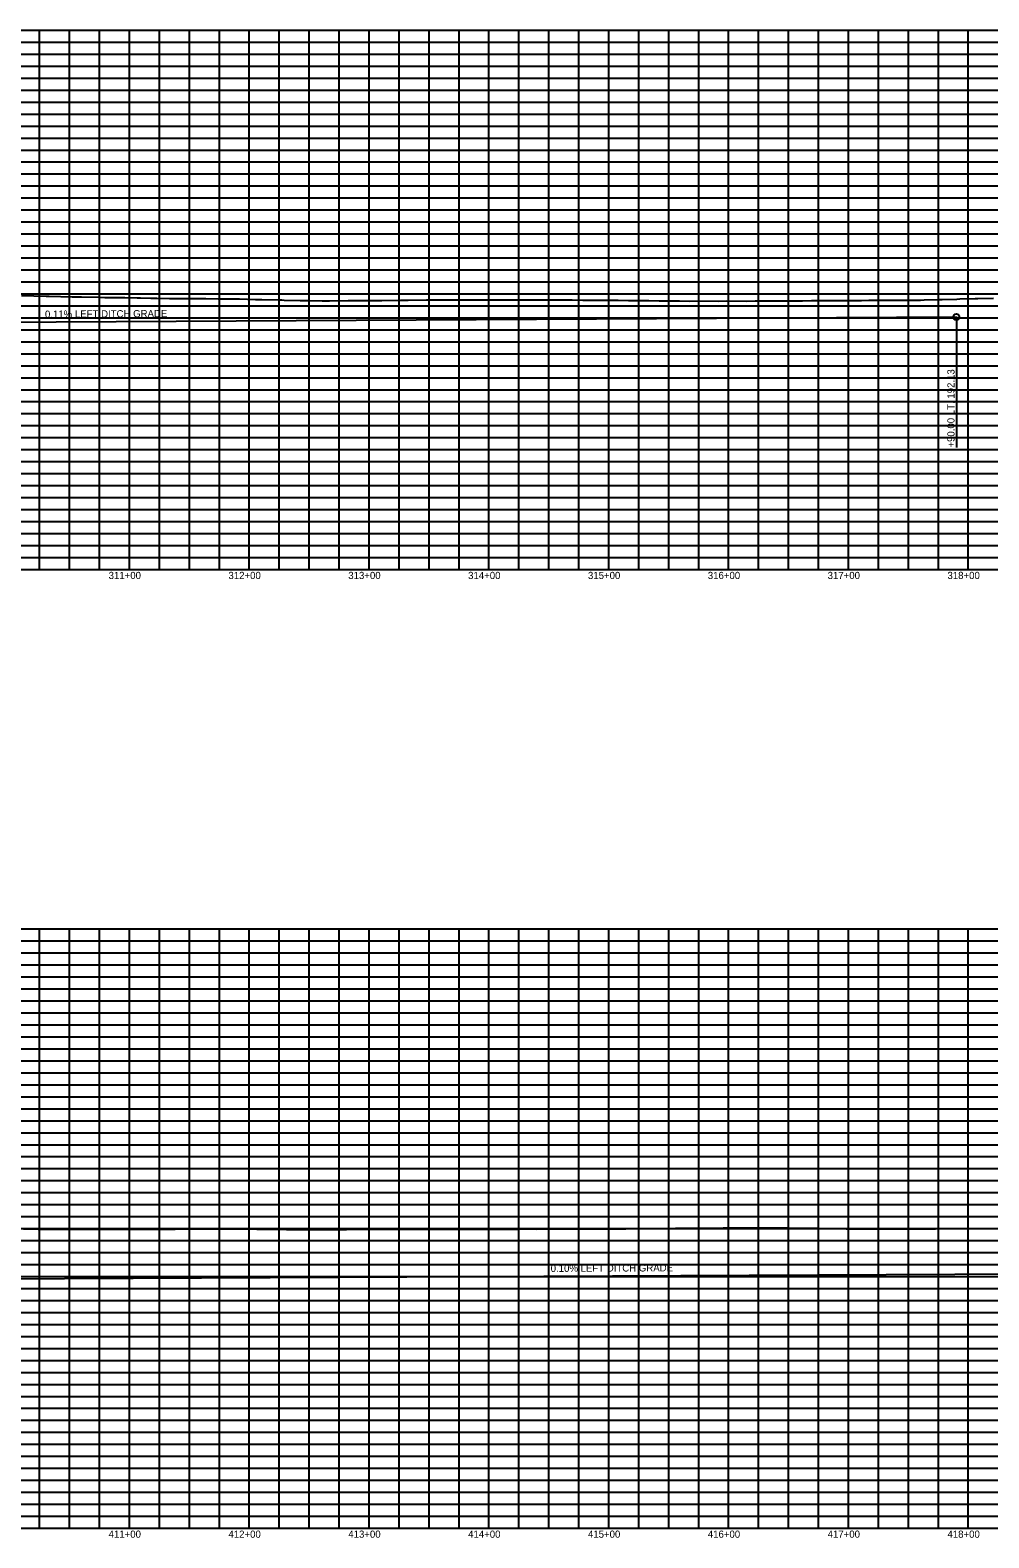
# Model space of a CAD drawing. Extents: x 1399671 to 1408349, y 1930471 to 1933387.
# Drawn here: x 1401341 to 1402141, y 1930471 to 1931729 of the extents above; entities that cross this region are included whole.
import ezdxf

# ---------------------------------------------------------------- set-up
doc = ezdxf.new("R2010")
doc.units = 0
for name, color, linetype in [('R_Exist Surface', 7, 'Continuous'), ('R_Grid', 7, 'Continuous'), ('R_Grid Annot', 7, 'Continuous'), ('R_Vert Alg', 7, 'Continuous'), ('R_Vert Alg Annot', 7, 'Continuous')]:
    doc.layers.add(name, color=color, linetype=linetype)

msp = doc.modelspace()

# ---------------------------------------------------------------- linework, layer by layer
at = {"layer": 'R_Exist Surface'}
for points in [[(1401334, 1931507.1), (1401354.6, 1931506.6), (1401354.6, 1931506.6), (1401357.3, 1931506.5), (1401376.5, 1931506.1), (1401377.1, 1931506.1), (1401380.5, 1931506), (1401384.2, 1931506), (1401398.3, 1931505.7), (1401403.7, 1931505.6), (1401406.3, 1931505.6), (1401417.2, 1931505.4), (1401419.9, 1931505.4), (1401420.2, 1931505.4), (1401430.7, 1931505.2), (1401433.5, 1931505.2), (1401442, 1931505), (1401444.2, 1931505), (1401447.1, 1931505), (1401457.7, 1931504.8), (1401460.7, 1931504.8), (1401463.9, 1931504.8), (1401471.2, 1931504.7), (1401474.2, 1931504.7), (1401484.7, 1931504.6), (1401485.7, 1931504.6), (1401487.8, 1931504.6), (1401498.1, 1931504.5), (1401501.3, 1931504.5), (1401507.6, 1931504.4), (1401511.6, 1931504.4), (1401516.1, 1931504.3), (1401529.4, 1931503.9), (1401530, 1931503.9), (1401534.7, 1931503.9), (1401548.3, 1931503.5), (1401551.3, 1931503.5), (1401553.2, 1931503.4), (1401566.7, 1931503.1), (1401571.7, 1931503.1), (1401573.1, 1931503), (1401585.1, 1931502.7), (1401591, 1931502.7), (1401606.8, 1931502.9), (1401613, 1931502.9), (1401628.6, 1931503.1), (1401634.9, 1931503.1), (1401650.4, 1931503.3), (1401656.9, 1931503.3), (1401672.1, 1931503.5), (1401676.7, 1931503.5), (1401686.8, 1931503.5), (1401691.4, 1931503.5), (1401701.5, 1931503.5), (1401706, 1931503.5), (1401716.2, 1931503.5), (1401720.7, 1931503.5), (1401730.9, 1931503.5), (1401735.4, 1931503.5), (1401745.5, 1931503.5), (1401750.1, 1931503.5), (1401760.2, 1931503.5), (1401764.8, 1931503.5), (1401774.9, 1931503.6), (1401779.4, 1931503.5), (1401789.6, 1931503.6), (1401793.5, 1931503.5), (1401802.4, 1931503.4), (1401806.3, 1931503.4), (1401815.2, 1931503.3), (1401819.1, 1931503.3), (1401827.9, 1931503.2), (1401832, 1931503.2), (1401840.7, 1931503.1), (1401844.8, 1931503.1), (1401853.5, 1931503), (1401857.6, 1931502.9), (1401866.3, 1931502.8), (1401870.4, 1931502.8), (1401879.1, 1931502.7), (1401883.2, 1931502.7), (1401891.9, 1931502.6), (1401899.4, 1931502.7), (1401915.4, 1931502.6), (1401922.8, 1931502.7), (1401938.9, 1931502.6), (1401946.3, 1931502.7), (1401962.4, 1931502.7), (1401969.7, 1931502.7), (1401975.4, 1931502.7), (1401985.9, 1931502.7), (1401993.2, 1931502.9), (1402010.5, 1931502.9), (1402017.1, 1931503.1), (1402035.1, 1931503.1), (1402041.1, 1931503.2), (1402059.7, 1931503.3), (1402065.2, 1931503.4), (1402084.3, 1931503.4), (1402087.4, 1931503.5), (1402099.5, 1931503.8), (1402102.3, 1931503.9), (1402114.7, 1931504.2), (1402117.1, 1931504.3), (1402129.9, 1931504.6), (1402132, 1931504.6), (1402145.1, 1931504.9)], [(1401335.7, 1930728.3), (1401347.9, 1930728.2), (1401348.7, 1930728.2), (1401349.6, 1930728.2), (1401372.8, 1930728.1), (1401373.6, 1930728.1), (1401374.5, 1930728.1), (1401397.7, 1930728.1), (1401398.5, 1930728.1), (1401420.9, 1930728.1), (1401422.7, 1930728.1), (1401424.4, 1930728.1), (1401446.8, 1930728.2), (1401448, 1930728.2), (1401461.1, 1930728.2), (1401462.4, 1930728.2), (1401475.5, 1930728.3), (1401476.8, 1930728.3), (1401489.9, 1930728.4), (1401491.3, 1930728.4), (1401504.2, 1930728.5), (1401505.5, 1930728.5), (1401517.3, 1930728.3), (1401518.6, 1930728.3), (1401530.4, 1930728.2), (1401531.7, 1930728.2), (1401543.5, 1930728.1), (1401555.3, 1930727.9), (1401556.6, 1930727.9), (1401578.5, 1930727.9), (1401580.9, 1930727.9), (1401602.9, 1930727.9), (1401605.2, 1930727.9), (1401627.7, 1930728), (1401629.8, 1930728), (1401652.5, 1930728), (1401654.4, 1930728), (1401666.6, 1930728), (1401667.7, 1930728), (1401679.8, 1930728), (1401680.9, 1930728), (1401693, 1930728), (1401694.1, 1930728), (1401706.2, 1930728), (1401707.3, 1930728), (1401719.9, 1930728.1), (1401721, 1930728.1), (1401733.7, 1930728.1), (1401734.6, 1930728.1), (1401747.4, 1930728.2), (1401748.3, 1930728.2), (1401749.2, 1930728.2), (1401762, 1930728.3), (1401763.5, 1930728.2), (1401785.9, 1930728.3), (1401808.7, 1930728.4), (1401809.7, 1930728.4), (1401823.5, 1930728.5), (1401824.1, 1930728.5), (1401837.8, 1930728.5), (1401838.4, 1930728.5), (1401852.2, 1930728.6), (1401852.7, 1930728.6), (1401866.5, 1930728.7), (1401867.1, 1930728.7), (1401879.8, 1930728.8), (1401880.3, 1930728.8), (1401893, 1930728.9), (1401893.5, 1930728.9), (1401906.2, 1930729), (1401906.7, 1930729), (1401919.5, 1930729.1), (1401919.9, 1930729.1), (1401932.8, 1930729.1), (1401933.2, 1930729.1), (1401933.6, 1930729.1), (1401946.4, 1930729.1), (1401946.8, 1930729.1), (1401959.7, 1930729.1), (1401960.1, 1930729.1), (1401973, 1930729.1), (1401973.3, 1930729.1), (1401997.4, 1930728.8), (1401997.8, 1930728.8), (1401998.2, 1930728.8), (1402022.2, 1930728.5), (1402022.6, 1930728.5), (1402023.3, 1930728.5), (1402040.9, 1930728.5), (1402041.7, 1930728.5), (1402059.1, 1930728.5), (1402060, 1930728.5), (1402077.3, 1930728.5), (1402078.4, 1930728.5), (1402095.5, 1930728.5), (1402096.9, 1930728.5), (1402116.6, 1930728.6), (1402117.8, 1930728.6), (1402137.6, 1930728.7), (1402138.2, 1930728.7), (1402152, 1930728.6)]]:
    msp.add_lwpolyline(points, dxfattribs=at)
at = {"layer": 'R_Grid'}
for p, q in [((1400324.2, 1931728.6), (1408324.2, 1931728.6)), ((1400324.2, 1931728.6), (1408324.2, 1931728.6)), ((1401349.2, 1931278.6), (1401349.2, 1931728.6)), ((1401374.2, 1931278.6), (1401374.2, 1931728.6)), ((1401399.2, 1931278.6), (1401399.2, 1931728.6)), ((1401424.2, 1931278.6), (1401424.2, 1931728.6)), ((1401449.2, 1931278.6), (1401449.2, 1931728.6)), ((1401474.2, 1931278.6), (1401474.2, 1931728.6)), ((1401499.2, 1931278.6), (1401499.2, 1931728.6)), ((1401524.2, 1931278.6), (1401524.2, 1931728.6)), ((1401549.2, 1931278.6), (1401549.2, 1931728.6)), ((1401574.2, 1931278.6), (1401574.2, 1931728.6)), ((1401599.2, 1931278.6), (1401599.2, 1931728.6)), ((1401624.2, 1931278.6), (1401624.2, 1931728.6)), ((1401649.2, 1931278.6), (1401649.2, 1931728.6)), ((1401674.2, 1931278.6), (1401674.2, 1931728.6)), ((1401699.2, 1931278.6), (1401699.2, 1931728.6)), ((1401724.2, 1931278.6), (1401724.2, 1931728.6)), ((1401749.2, 1931278.6), (1401749.2, 1931728.6)), ((1401774.2, 1931278.6), (1401774.2, 1931728.6)), ((1401799.2, 1931278.6), (1401799.2, 1931728.6)), ((1401824.2, 1931278.6), (1401824.2, 1931728.6)), ((1401849.2, 1931278.6), (1401849.2, 1931728.6)), ((1401874.2, 1931278.6), (1401874.2, 1931728.6)), ((1401899.2, 1931278.6), (1401899.2, 1931728.6)), ((1401924.2, 1931278.6), (1401924.2, 1931728.6)), ((1401949.2, 1931278.6), (1401949.2, 1931728.6)), ((1401974.2, 1931278.6), (1401974.2, 1931728.6)), ((1401999.2, 1931278.6), (1401999.2, 1931728.6)), ((1402024.2, 1931278.6), (1402024.2, 1931728.6)), ((1402049.2, 1931278.6), (1402049.2, 1931728.6)), ((1402074.2, 1931278.6), (1402074.2, 1931728.6)), ((1402099.2, 1931278.6), (1402099.2, 1931728.6)), ((1402124.2, 1931278.6), (1402124.2, 1931728.6)), ((1400324.2, 1931718.6), (1408324.2, 1931718.6)), ((1400324.2, 1931708.6), (1408324.2, 1931708.6)), ((1400324.2, 1931698.6), (1408324.2, 1931698.6)), ((1400324.2, 1931688.6), (1408324.2, 1931688.6)), ((1400324.2, 1931678.6), (1408324.2, 1931678.6)), ((1400324.2, 1931668.6), (1408324.2, 1931668.6)), ((1400324.2, 1931658.6), (1408324.2, 1931658.6)), ((1400324.2, 1931648.6), (1408324.2, 1931648.6)), ((1400324.2, 1931638.6), (1408324.2, 1931638.6)), ((1400324.2, 1931628.6), (1408324.2, 1931628.6)), ((1400324.2, 1931618.6), (1408324.2, 1931618.6)), ((1400324.2, 1931608.6), (1408324.2, 1931608.6)), ((1400324.2, 1931598.6), (1408324.2, 1931598.6)), ((1400324.2, 1931588.6), (1408324.2, 1931588.6)), ((1400324.2, 1931578.6), (1408324.2, 1931578.6)), ((1400324.2, 1931568.6), (1408324.2, 1931568.6)), ((1400324.2, 1931558.6), (1408324.2, 1931558.6)), ((1400324.2, 1931548.6), (1408324.2, 1931548.6)), ((1400324.2, 1931538.6), (1408324.2, 1931538.6)), ((1400324.2, 1931528.6), (1408324.2, 1931528.6)), ((1400324.2, 1931518.6), (1408324.2, 1931518.6)), ((1400324.2, 1931508.6), (1408324.2, 1931508.6)), ((1400324.2, 1931498.6), (1408324.2, 1931498.6)), ((1400324.2, 1931488.6), (1408324.2, 1931488.6)), ((1400324.2, 1931478.6), (1408324.2, 1931478.6)), ((1400324.2, 1931468.6), (1408324.2, 1931468.6)), ((1400324.2, 1931458.6), (1408324.2, 1931458.6)), ((1400324.2, 1931448.6), (1408324.2, 1931448.6)), ((1400324.2, 1931438.6), (1408324.2, 1931438.6)), ((1400324.2, 1931428.6), (1408324.2, 1931428.6)), ((1400324.2, 1931418.6), (1408324.2, 1931418.6)), ((1400324.2, 1931408.6), (1408324.2, 1931408.6)), ((1400324.2, 1931398.6), (1408324.2, 1931398.6)), ((1400324.2, 1931388.6), (1408324.2, 1931388.6)), ((1400324.2, 1931378.6), (1408324.2, 1931378.6)), ((1400324.2, 1931368.6), (1408324.2, 1931368.6)), ((1400324.2, 1931358.6), (1408324.2, 1931358.6)), ((1400324.2, 1931348.6), (1408324.2, 1931348.6)), ((1400324.2, 1931338.6), (1408324.2, 1931338.6)), ((1400324.2, 1931328.6), (1408324.2, 1931328.6)), ((1400324.2, 1931318.6), (1408324.2, 1931318.6)), ((1400324.2, 1931308.6), (1408324.2, 1931308.6)), ((1400324.2, 1931298.6), (1408324.2, 1931298.6)), ((1400324.2, 1931288.6), (1408324.2, 1931288.6)), ((1400324.2, 1931278.6), (1408324.2, 1931278.6)), ((1400324.2, 1930978.6), (1407124.2, 1930978.6)), ((1400324.2, 1930978.6), (1407124.2, 1930978.6)), ((1401349.2, 1930478.6), (1401349.2, 1930978.6)), ((1401374.2, 1930478.6), (1401374.2, 1930978.6)), ((1401399.2, 1930478.6), (1401399.2, 1930978.6)), ((1401424.2, 1930478.6), (1401424.2, 1930978.6)), ((1401449.2, 1930478.6), (1401449.2, 1930978.6)), ((1401474.2, 1930478.6), (1401474.2, 1930978.6)), ((1401499.2, 1930478.6), (1401499.2, 1930978.6)), ((1401524.2, 1930478.6), (1401524.2, 1930978.6)), ((1401549.2, 1930478.6), (1401549.2, 1930978.6)), ((1401574.2, 1930478.6), (1401574.2, 1930978.6)), ((1401599.2, 1930478.6), (1401599.2, 1930978.6)), ((1401624.2, 1930478.6), (1401624.2, 1930978.6)), ((1401649.2, 1930478.6), (1401649.2, 1930978.6)), ((1401674.2, 1930478.6), (1401674.2, 1930978.6)), ((1401699.2, 1930478.6), (1401699.2, 1930978.6)), ((1401724.2, 1930478.6), (1401724.2, 1930978.6)), ((1401749.2, 1930478.6), (1401749.2, 1930978.6)), ((1401774.2, 1930478.6), (1401774.2, 1930978.6)), ((1401799.2, 1930478.6), (1401799.2, 1930978.6)), ((1401824.2, 1930478.6), (1401824.2, 1930978.6)), ((1401849.2, 1930478.6), (1401849.2, 1930978.6)), ((1401874.2, 1930478.6), (1401874.2, 1930978.6)), ((1401899.2, 1930478.6), (1401899.2, 1930978.6)), ((1401924.2, 1930478.6), (1401924.2, 1930978.6)), ((1401949.2, 1930478.6), (1401949.2, 1930978.6)), ((1401974.2, 1930478.6), (1401974.2, 1930978.6)), ((1401999.2, 1930478.6), (1401999.2, 1930978.6)), ((1402024.2, 1930478.6), (1402024.2, 1930978.6)), ((1402049.2, 1930478.6), (1402049.2, 1930978.6)), ((1402074.2, 1930478.6), (1402074.2, 1930978.6)), ((1402099.2, 1930478.6), (1402099.2, 1930978.6)), ((1402124.2, 1930478.6), (1402124.2, 1930978.6)), ((1400324.2, 1930968.6), (1407124.2, 1930968.6)), ((1400324.2, 1930958.6), (1407124.2, 1930958.6)), ((1400324.2, 1930948.6), (1407124.2, 1930948.6)), ((1400324.2, 1930938.6), (1407124.2, 1930938.6)), ((1400324.2, 1930928.6), (1407124.2, 1930928.6)), ((1400324.2, 1930918.6), (1407124.2, 1930918.6)), ((1400324.2, 1930908.6), (1407124.2, 1930908.6)), ((1400324.2, 1930898.6), (1407124.2, 1930898.6)), ((1400324.2, 1930888.6), (1407124.2, 1930888.6)), ((1400324.2, 1930878.6), (1407124.2, 1930878.6)), ((1400324.2, 1930868.6), (1407124.2, 1930868.6)), ((1400324.2, 1930858.6), (1407124.2, 1930858.6)), ((1400324.2, 1930848.6), (1407124.2, 1930848.6)), ((1400324.2, 1930838.6), (1407124.2, 1930838.6)), ((1400324.2, 1930828.6), (1407124.2, 1930828.6)), ((1400324.2, 1930818.6), (1407124.2, 1930818.6)), ((1400324.2, 1930808.6), (1407124.2, 1930808.6)), ((1400324.2, 1930798.6), (1407124.2, 1930798.6)), ((1400324.2, 1930788.6), (1407124.2, 1930788.6)), ((1400324.2, 1930778.6), (1407124.2, 1930778.6)), ((1400324.2, 1930768.6), (1407124.2, 1930768.6)), ((1400324.2, 1930758.6), (1407124.2, 1930758.6)), ((1400324.2, 1930748.6), (1407124.2, 1930748.6)), ((1400324.2, 1930738.6), (1407124.2, 1930738.6)), ((1400324.2, 1930728.6), (1407124.2, 1930728.6)), ((1400324.2, 1930718.6), (1407124.2, 1930718.6)), ((1400324.2, 1930708.6), (1407124.2, 1930708.6)), ((1400324.2, 1930698.6), (1407124.2, 1930698.6)), ((1400324.2, 1930688.6), (1407124.2, 1930688.6)), ((1400324.2, 1930678.6), (1407124.2, 1930678.6)), ((1400324.2, 1930668.6), (1407124.2, 1930668.6)), ((1400324.2, 1930658.6), (1407124.2, 1930658.6)), ((1400324.2, 1930648.6), (1407124.2, 1930648.6)), ((1400324.2, 1930638.6), (1407124.2, 1930638.6)), ((1400324.2, 1930628.6), (1407124.2, 1930628.6)), ((1400324.2, 1930618.6), (1407124.2, 1930618.6)), ((1400324.2, 1930608.6), (1407124.2, 1930608.6)), ((1400324.2, 1930598.6), (1407124.2, 1930598.6)), ((1400324.2, 1930588.6), (1407124.2, 1930588.6)), ((1400324.2, 1930578.6), (1407124.2, 1930578.6)), ((1400324.2, 1930568.6), (1407124.2, 1930568.6)), ((1400324.2, 1930558.6), (1407124.2, 1930558.6)), ((1400324.2, 1930548.6), (1407124.2, 1930548.6)), ((1400324.2, 1930538.6), (1407124.2, 1930538.6)), ((1400324.2, 1930528.6), (1407124.2, 1930528.6)), ((1400324.2, 1930518.6), (1407124.2, 1930518.6)), ((1400324.2, 1930508.6), (1407124.2, 1930508.6)), ((1400324.2, 1930498.6), (1407124.2, 1930498.6)), ((1400324.2, 1930488.6), (1407124.2, 1930488.6)), ((1400324.2, 1930478.6), (1407124.2, 1930478.6))]:
    msp.add_line(p, q, dxfattribs=at)
at = {"layer": 'R_Vert Alg'}
for p, q in [((1400724.2, 1931481.6), (1402114.2, 1931489.3)), ((1400924.2, 1930684.7), (1402758.2, 1930693.8))]:
    msp.add_line(p, q, dxfattribs=at)
at = {"layer": 'R_Vert Alg Annot'}
for p, q in [((1402114.2, 1931489.3), (1402114.2, 1931464.3)), ((1402114.2, 1931464.3), (1402114.2, 1931380.3))]:
    msp.add_line(p, q, dxfattribs=at)
msp.add_circle((1402114.2, 1931489.3), 2.5, dxfattribs=at)

# ---------------------------------------------------------------- texts
at = {"layer": 'R_Grid Annot'}
for s, p in [('311+00', (1401406.8, 1931270.6)), ('312+00', (1401506.8, 1931270.6)), ('313+00', (1401606.8, 1931270.6)), ('314+00', (1401706.8, 1931270.6)), ('315+00', (1401806.8, 1931270.6)), ('316+00', (1401906.8, 1931270.6)), ('317+00', (1402006.8, 1931270.6)), ('318+00', (1402106.8, 1931270.6)), ('411+00', (1401406.8, 1930470.6)), ('412+00', (1401506.8, 1930470.6)), ('413+00', (1401606.8, 1930470.6)), ('414+00', (1401706.8, 1930470.6)), ('415+00', (1401806.8, 1930470.6)), ('416+00', (1401906.8, 1930470.6)), ('417+00', (1402006.8, 1930470.6)), ('418+00', (1402106.8, 1930470.6))]:
    msp.add_text(s, height=6, dxfattribs=at).set_placement(p)
at = {"layer": 'R_Vert Alg Annot'}
for s, rotation, p in [('0.11% LEFT DITCH GRADE', 0.3153, (1401353.7, 1931488.6)), ('+90.00 LT. 192.13', 90, (1402112.7, 1931380.3)), ('0.10% LEFT DITCH GRADE', 0.2859, (1401775.7, 1930692.4))]:
    msp.add_text(s, height=6, rotation=rotation, dxfattribs=at).set_placement(p)

doc.saveas('drawing.dxf')
